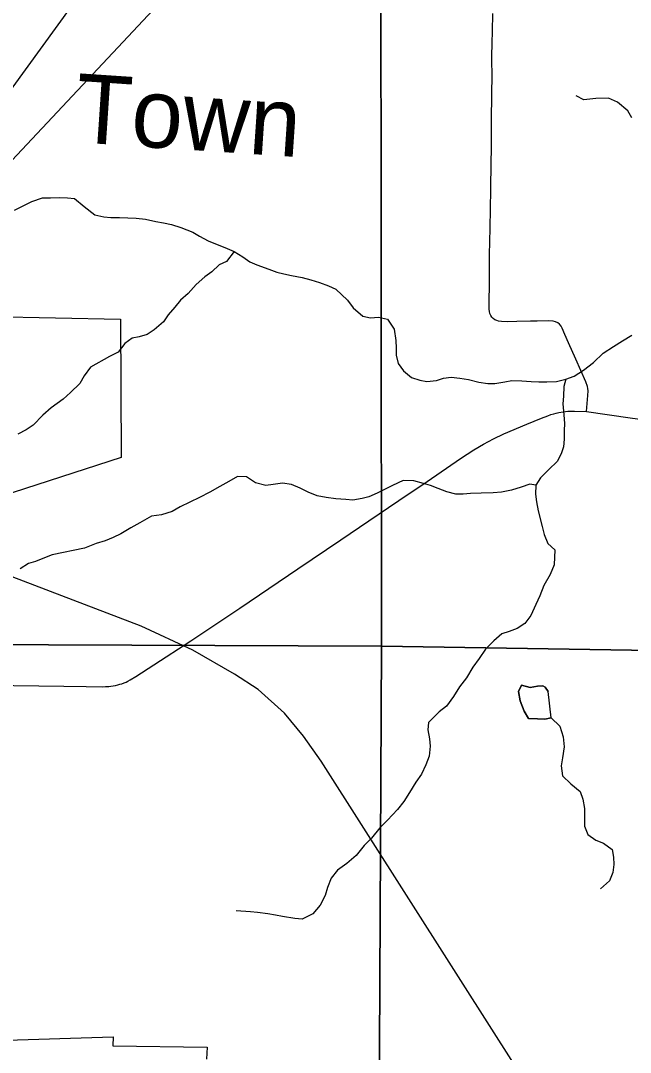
# Model space of a CAD drawing. Extents: x 0 to 34, y 0 to 22.
# Drawn here: x 10.17 to 11.007, y 17.551 to 18.968 of the extents above; entities that cross this region are included whole.
import ezdxf

# ---------------------------------------------------------------- set-up
doc = ezdxf.new("R2010")
doc.units = 0
for name, color, linetype in [('GM_X_Corporation', 7, 'Continuous'), ('GM_X_County_Road', 7, 'Continuous'), ('GM_X_Minor_Lake', 7, 'Continuous'), ('GM_X_Minor_River', 7, 'Continuous'), ('GM_X_Minor_River_Text', 7, 'Continuous'), ('GM_X_Rail_Line', 7, 'Continuous'), ('GM_X_Section', 7, 'Continuous'), ('GM_X_Township_Road', 7, 'Continuous'), ('SH_Text', 7, 'Continuous')]:
    doc.layers.add(name, color=color, linetype=linetype)

msp = doc.modelspace()

# ---------------------------------------------------------------- linework, layer by layer
at = {"layer": 'GM_X_Corporation'}
for points in [[(9.8598, 18.567), (10.3068, 18.5578), (10.3078, 18.3681), (10.1424, 18.3144)], [(9.8435, 17.5579), (10.2967, 17.5721), (10.2961, 17.56), (10.4255, 17.558), (10.4249, 17.5418)]]:
    msp.add_lwpolyline(points, dxfattribs=at)
at = {"layer": 'GM_X_County_Road'}
for points in [[(10.2968, 18.0544), (10.2998, 18.0548), (10.3028, 18.0556), (10.3058, 18.0565), (10.3086, 18.0573), (10.3118, 18.0583), (10.3144, 18.0594), (10.3168, 18.0607), (10.3198, 18.0624), (10.3277, 18.0671), (10.3693, 18.0943), (10.4032, 18.1162), (10.4703, 18.161), (10.5501, 18.2149), (10.6091, 18.255), (10.6477, 18.2811), (10.6888, 18.309), (10.7275, 18.3349), (10.7736, 18.3665), (10.7918, 18.3784), (10.8052, 18.3863), (10.8189, 18.3937), (10.833, 18.4004), (10.8644, 18.4139), (10.8845, 18.4222), (10.8933, 18.4254), (10.8976, 18.4269), (10.9015, 18.4281), (10.9048, 18.429), (10.9083, 18.4298), (10.9144, 18.4309), (10.9207, 18.4316), (10.9249, 18.4318), (10.9301, 18.4318), (10.9466, 18.4311)], [(10.9466, 18.4311), (11.0064, 18.4226), (11.0402, 18.4179), (11.1079, 18.4087), (11.1448, 18.4035), (11.1633, 18.401), (11.1787, 18.3988), (11.1941, 18.3967), (11.2102, 18.3945), (11.2305, 18.3918), (11.2688, 18.3863), (11.2856, 18.3839), (11.3291, 18.3777), (11.3396, 18.3761), (11.3528, 18.3743), (11.3639, 18.3727), (11.3819, 18.3703)], [(10.0784, 18.0561), (10.0983, 18.0557), (10.1604, 18.055), (10.2287, 18.054), (10.2597, 18.0534), (10.2814, 18.0532), (10.2861, 18.0533), (10.2907, 18.0536), (10.2934, 18.054), (10.2968, 18.0544)]]:
    msp.add_lwpolyline(points, dxfattribs=at)
at = {"layer": 'GM_X_Minor_Lake'}
for points in [[(10.894, 18.0464), (10.8898, 18.0525), (10.8864, 18.0544), (10.8792, 18.0537), (10.8693, 18.0522), (10.8572, 18.0553), (10.853, 18.0466), (10.8552, 18.0336), (10.8608, 18.0195), (10.8669, 18.0096), (10.8794, 18.0092), (10.8893, 18.0084), (10.898, 18.0102)], [(10.898, 18.0103), (10.8893, 18.0084), (10.8794, 18.0092), (10.8669, 18.0096), (10.8608, 18.0195), (10.8552, 18.0336), (10.853, 18.0466), (10.8572, 18.0553), (10.8693, 18.0522), (10.8792, 18.0537), (10.8864, 18.0544), (10.8898, 18.0525), (10.894, 18.0464)], [(10.898, 18.0102), (10.894, 18.0464)]]:
    msp.add_lwpolyline(points, dxfattribs=at)
at = {"layer": 'GM_X_Minor_River'}
for points in [[(11.0089, 18.8343), (11.0031, 18.8441), (10.989, 18.8558), (10.9768, 18.8614), (10.9593, 18.8609), (10.943, 18.8593), (10.9323, 18.8645)], [(10.1609, 18.7075), (10.1749, 18.7144), (10.1851, 18.7198), (10.1995, 18.7245), (10.2105, 18.7246), (10.2223, 18.725), (10.2337, 18.7247), (10.2436, 18.7237), (10.2566, 18.7127), (10.2715, 18.7011), (10.2837, 18.6985), (10.2932, 18.6978), (10.3053, 18.6975), (10.3167, 18.6972), (10.3281, 18.6965), (10.3411, 18.6955), (10.3551, 18.6922), (10.3658, 18.6904), (10.3768, 18.6882), (10.3894, 18.6841), (10.4058, 18.6774), (10.4153, 18.6721), (10.4272, 18.6657), (10.4394, 18.6605), (10.45, 18.6564), (10.4626, 18.6508), (10.4745, 18.6436), (10.4844, 18.6365), (10.4939, 18.6324), (10.5103, 18.6268), (10.5214, 18.6227), (10.5309, 18.6201), (10.5415, 18.6179), (10.556, 18.6154), (10.5678, 18.612), (10.58, 18.6083), (10.5922, 18.6038), (10.6021, 18.5994), (10.6182, 18.5839), (10.6259, 18.5737), (10.6392, 18.562), (10.6499, 18.5598), (10.6609, 18.5606), (10.6731, 18.5581), (10.6823, 18.5441), (10.6847, 18.5289), (10.6852, 18.5182), (10.6853, 18.5087), (10.6877, 18.4973), (10.695, 18.4868), (10.7064, 18.4777), (10.7175, 18.474), (10.7274, 18.4722), (10.7403, 18.4738), (10.7501, 18.4769), (10.7608, 18.4781), (10.7725, 18.4771), (10.7843, 18.4749), (10.7988, 18.4716), (10.811, 18.4694), (10.8208, 18.4698), (10.8345, 18.4718), (10.844, 18.4738), (10.8577, 18.4735), (10.8706, 18.4725), (10.8812, 18.4718), (10.8919, 18.4719), (10.9052, 18.4724), (10.918, 18.4755)], [(10.4626, 18.6508), (10.4521, 18.6374), (10.4423, 18.6324), (10.4321, 18.6232), (10.4223, 18.6163), (10.4106, 18.6055), (10.3997, 18.5933), (10.3891, 18.5841), (10.3812, 18.5745), (10.3722, 18.5638), (10.3658, 18.5543), (10.353, 18.5435), (10.3431, 18.537), (10.3325, 18.5339), (10.3227, 18.5319), (10.3128, 18.5246), (10.3034, 18.5127), (10.2917, 18.5066), (10.2653, 18.4919), (10.257, 18.4801), (10.2506, 18.4694), (10.2378, 18.4571), (10.228, 18.4483), (10.2114, 18.4364), (10.2001, 18.4261), (10.1869, 18.4123), (10.1771, 18.4061), (10.1657, 18.3999)], [(10.918, 18.4755), (10.9294, 18.4798), (10.9423, 18.4878), (10.9562, 18.4986), (10.9694, 18.5112), (10.9834, 18.5205), (10.9959, 18.5281), (11.0087, 18.5362)], [(10.918, 18.4755), (10.9155, 18.4656), (10.9148, 18.4523), (10.9142, 18.4416), (10.9154, 18.4264), (10.9163, 18.4146), (10.916, 18.4051), (10.9157, 18.393), (10.915, 18.3827), (10.9117, 18.3732), (10.9061, 18.3625), (10.8948, 18.3514), (10.8831, 18.3399), (10.8767, 18.33), (10.8764, 18.3178), (10.878, 18.3072), (10.88, 18.2946), (10.8855, 18.2734), (10.8883, 18.262), (10.8933, 18.2499), (10.9029, 18.2412)], [(10.8767, 18.33), (10.8687, 18.3314), (10.8566, 18.3271), (10.8433, 18.3232), (10.8297, 18.3205), (10.8183, 18.3193), (10.802, 18.3188), (10.7871, 18.3186), (10.7773, 18.3178), (10.767, 18.3174), (10.7548, 18.3207), (10.7426, 18.3255), (10.7324, 18.3293), (10.7225, 18.3322), (10.7095, 18.3359), (10.6947, 18.3366), (10.6803, 18.3296), (10.6701, 18.3246), (10.6591, 18.3192), (10.6478, 18.3138), (10.6383, 18.3115), (10.6258, 18.3095), (10.6159, 18.3105), (10.6022, 18.3112), (10.5889, 18.313), (10.5767, 18.3152), (10.5641, 18.3204), (10.5535, 18.3257), (10.5413, 18.3309), (10.5291, 18.3327), (10.5162, 18.3307), (10.5063, 18.3295), (10.4918, 18.3332), (10.4796, 18.3415), (10.4675, 18.3417), (10.4554, 18.3352), (10.4429, 18.3283), (10.4293, 18.3205), (10.4153, 18.3132), (10.4017, 18.3067), (10.3888, 18.3001), (10.3774, 18.2939), (10.363, 18.2893), (10.349, 18.2876), (10.3331, 18.2784), (10.321, 18.2715), (10.307, 18.263), (10.2968, 18.258), (10.2858, 18.2537), (10.2733, 18.2498), (10.2571, 18.2436)], [(10.2571, 18.2436), (10.2128, 18.2345), (10.2021, 18.2303), (10.19, 18.2251), (10.1805, 18.2224), (10.169, 18.2149)], [(10.9029, 18.2412), (10.9022, 18.2204), (10.8968, 18.2075), (10.888, 18.1923), (10.8823, 18.1779), (10.8769, 18.1661), (10.87, 18.151), (10.8617, 18.14), (10.8514, 18.1332), (10.8404, 18.1291), (10.8301, 18.1257), (10.8194, 18.1162), (10.8076, 18.1049), (10.7992, 18.092), (10.7904, 18.0799), (10.7817, 18.0655), (10.7721, 18.053), (10.7637, 18.0397), (10.7542, 18.0265), (10.7443, 18.0185), (10.7294, 18.0042), (10.7286, 17.9939), (10.7309, 17.9817), (10.732, 17.9715), (10.7304, 17.9578), (10.7258, 17.9457), (10.7201, 17.9331), (10.7121, 17.9222), (10.7033, 17.9078), (10.6956, 17.8953), (10.6872, 17.8847), (10.6731, 17.8699), (10.6629, 17.8593), (10.6514, 17.8453), (10.6411, 17.8351), (10.6301, 17.8215), (10.6175, 17.8101), (10.6046, 17.801), (10.5958, 17.7901), (10.5908, 17.7775), (10.5877, 17.7662), (10.5809, 17.7529), (10.5709, 17.7412), (10.5561, 17.734), (10.5462, 17.7348), (10.5292, 17.7375), (10.5197, 17.7395), (10.5091, 17.7414), (10.4946, 17.743), (10.4851, 17.7438), (10.4654, 17.7454)], [(10.898, 18.0102), (10.9098, 17.9988), (10.9146, 17.9843), (10.9157, 17.9707), (10.9134, 17.9555), (10.9115, 17.9445), (10.9133, 17.9308), (10.925, 17.9197), (10.9379, 17.909), (10.9413, 17.8987), (10.9439, 17.8858), (10.9438, 17.8615), (10.9483, 17.8501), (10.9593, 17.8424), (10.9699, 17.8382), (10.9817, 17.8294), (10.9835, 17.8191), (10.9839, 17.8089), (10.9827, 17.7978), (10.9781, 17.7865), (10.9655, 17.7755)]]:
    msp.add_lwpolyline(points, dxfattribs=at)
at = {"layer": 'GM_X_Rail_Line'}
msp.add_lwpolyline([(11.5404, 16.5859), (11.5289, 16.5995), (11.4762, 16.6651), (11.2305, 16.9587), (11.1455, 17.0668), (11.0594, 17.202), (10.8227, 17.5728), (10.5824, 17.9507), (10.5577, 17.9852), (10.5319, 18.0169), (10.4959, 18.0492), (10.4634, 18.0702), (10.4059, 18.1032), (10.3351, 18.1361), (9.8403, 18.3254), (9.7839, 18.3345), (9.7112, 18.3327), (9.6038, 18.3127), (9.5474, 18.32), (9.5165, 18.3345), (9.4983, 18.3528), (9.4692, 18.3928), (9.2764, 18.7478), (9.2289, 18.8396)], dxfattribs=at)
at = {"layer": 'GM_X_Section'}
for points in [[(10.6641, 19.1128), (10.6649, 18.109), (9.6357, 18.1129), (9.6363, 19.1257)], [(11.6646, 19.0944), (11.6666, 18.0929), (10.6649, 18.109), (10.6641, 19.1128)], [(9.6357, 18.1129), (10.6649, 18.109), (10.6598, 17.0956), (9.6334, 17.0953)], [(11.6666, 18.0929), (11.6623, 17.0784), (10.6598, 17.0956), (10.6649, 18.109)]]:
    msp.add_lwpolyline(points, close=True, dxfattribs=at)
at = {"layer": 'GM_X_Township_Road'}
msp.add_lwpolyline([(10.9466, 18.4311), (10.9484, 18.4531), (10.9487, 18.4594), (10.9485, 18.4626), (10.9478, 18.4657), (10.9456, 18.4717), (10.9318, 18.5029), (10.9218, 18.5256), (10.9169, 18.537), (10.9132, 18.5456), (10.9116, 18.5484), (10.9095, 18.5509), (10.9069, 18.5529), (10.9039, 18.5543), (10.9008, 18.555), (10.8944, 18.5555), (10.8789, 18.5552), (10.8696, 18.5552), (10.851, 18.5547), (10.8386, 18.5543), (10.8297, 18.5546), (10.8258, 18.5552), (10.8232, 18.556), (10.8207, 18.5569), (10.8182, 18.5588), (10.8165, 18.5608), (10.8149, 18.563), (10.8138, 18.5658), (10.8133, 18.5685), (10.8129, 18.5715), (10.8128, 18.5748), (10.8127, 18.5806), (10.8132, 18.6075), (10.8135, 18.6212), (10.8134, 18.6463), (10.8143, 18.6828), (10.8153, 18.7359), (10.8157, 18.7732), (10.8161, 18.7918), (10.8159, 18.8042), (10.8161, 18.8135), (10.8162, 18.8289), (10.8162, 18.8382), (10.8164, 18.8599), (10.8166, 18.8723), (10.8168, 18.8878), (10.8167, 18.9187), (10.817, 18.9377), (10.8173, 18.9529), (10.818, 18.9777)], dxfattribs=at)
at = {"layer": 'SH_Text'}
msp.add_lwpolyline([(11.0666, 20.1282), (9.8384, 18.436), (11.4252, 20.1282)], close=True, dxfattribs=at)

# ---------------------------------------------------------------- texts
at = {"layer": 'GM_X_Minor_River_Text'}
msp.add_text('Town', height=0.09472, rotation=356.1633, dxfattribs=at).set_placement((10.2422, 18.8012))

doc.saveas('drawing.dxf')
